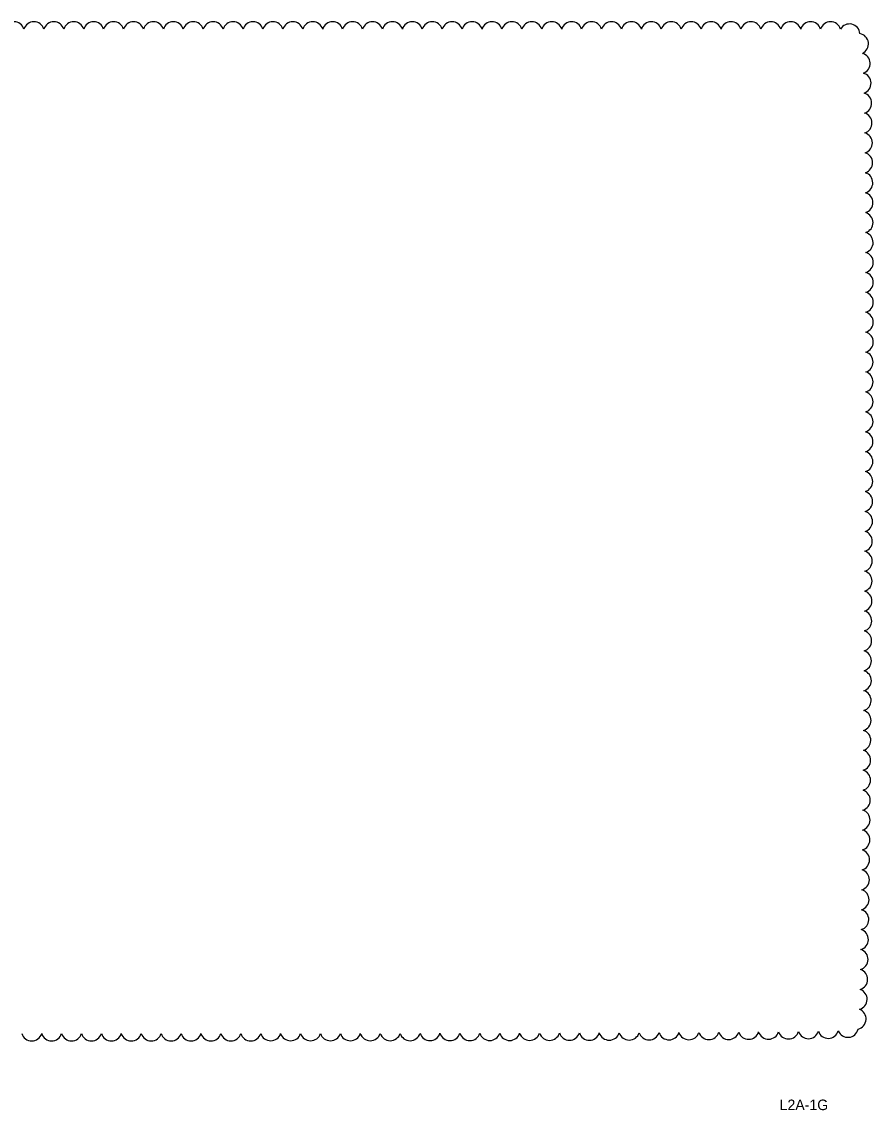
# Model space of a CAD drawing. Extents: x -811 to 10319, y -2309 to 9962.
# Drawn here: x -803.18 to -795.1, y -2284.04 to -2273.71 of the extents above; entities that cross this region are included whole.
import ezdxf

# ---------------------------------------------------------------- set-up
doc = ezdxf.new("R2010")
doc.units = 0
doc.layers.add('ScratchEle_dp', color=7, linetype='Continuous')
doc.layers.add('SheetLines_dp', color=7, linetype='Continuous')

msp = doc.modelspace()

# ---------------------------------------------------------------- linework, layer by layer
at = {"layer": 'ScratchEle_dp'}
for centre, radius, start, end in [((-803.255, -2273.807), 0.0991, 17.5008, 162.5008), ((-803.066, -2273.807), 0.0991, 17.5, 162.5), ((-802.877, -2273.807), 0.0991, 17.5, 162.5), ((-802.688, -2273.807), 0.0991, 17.5, 162.5), ((-802.499, -2273.807), 0.0991, 17.5, 162.5), ((-802.31, -2273.807), 0.0991, 17.5, 162.5), ((-802.121, -2273.807), 0.0991, 17.5, 162.5), ((-801.932, -2273.807), 0.0991, 17.5, 162.5), ((-801.743, -2273.807), 0.0991, 17.5, 162.5), ((-801.554, -2273.807), 0.0991, 17.5, 162.5), ((-801.365, -2273.807), 0.0991, 17.5, 162.5), ((-801.176, -2273.807), 0.0991, 17.5, 162.5), ((-800.987, -2273.807), 0.0991, 17.5, 162.5), ((-800.798, -2273.807), 0.0991, 17.5, 162.5), ((-800.609, -2273.807), 0.0991, 17.5, 162.5), ((-800.42, -2273.807), 0.0991, 17.5, 162.5), ((-800.231, -2273.807), 0.0991, 17.5, 162.5), ((-800.042, -2273.807), 0.0991, 17.5, 162.5), ((-799.853, -2273.807), 0.0991, 17.5, 162.5), ((-799.664, -2273.807), 0.0991, 17.5, 162.5), ((-799.475, -2273.807), 0.0991, 17.5, 162.5), ((-799.286, -2273.807), 0.0991, 17.5, 162.5), ((-799.097, -2273.807), 0.0991, 17.5, 162.5), ((-798.908, -2273.807), 0.0991, 17.5, 162.5), ((-798.719, -2273.807), 0.0991, 17.5, 162.5), ((-798.53, -2273.807), 0.0991, 17.5, 162.5), ((-798.341, -2273.807), 0.0991, 17.5, 162.5), ((-798.152, -2273.807), 0.0991, 17.5, 162.5), ((-797.963, -2273.807), 0.0991, 17.5, 162.5), ((-797.774, -2273.807), 0.0991, 17.5, 162.5), ((-797.585, -2273.807), 0.0991, 17.5, 162.5), ((-797.396, -2273.807), 0.0991, 17.5, 162.5), ((-797.207, -2273.807), 0.0991, 17.5, 162.5), ((-797.018, -2273.807), 0.0991, 17.5, 162.5), ((-796.829, -2273.807), 0.0991, 17.5, 162.5), ((-796.64, -2273.807), 0.0991, 17.5, 162.5), ((-796.451, -2273.807), 0.0991, 17.5, 162.5), ((-796.262, -2273.807), 0.0991, 17.5, 162.5), ((-796.073, -2273.807), 0.0991, 17.5, 162.5), ((-795.884, -2273.807), 0.0991, 17.5, 162.5), ((-795.695, -2273.807), 0.0991, 17.5, 162.5), ((-795.506, -2273.807), 0.0991, 17.5, 162.5), ((-795.326, -2273.828), 0.099, 4.4162, 149.4162), ((-795.245, -2273.918), 0.0992, 294.7802, 79.7802), ((-795.229, -2274.104), 0.0991, 290.3649, 75.3649), ((-795.221, -2274.292), 0.0991, 289.3839, 74.3839), ((-795.215, -2274.481), 0.0991, 288.8712, 73.8712), ((-795.212, -2274.669), 0.0991, 288.5423, 73.5423), ((-795.208, -2274.858), 0.0991, 288.3081, 73.3081), ((-795.206, -2275.047), 0.0991, 288.1304, 73.1304), ((-795.204, -2275.236), 0.0991, 287.9896, 72.9896), ((-795.203, -2275.425), 0.0991, 287.8744, 72.8744), ((-795.202, -2275.614), 0.0991, 287.778, 72.778), ((-795.201, -2275.803), 0.0991, 287.6956, 72.6956), ((-795.2, -2275.992), 0.0991, 287.6243, 72.6243), ((-795.2, -2276.181), 0.0991, 287.5617, 72.5617), ((-795.2, -2276.37), 0.0991, 287.5062, 72.5062), ((-795.2, -2276.559), 0.0991, 287.4565, 72.4565), ((-795.2, -2276.748), 0.0991, 287.4117, 72.4117), ((-795.201, -2276.937), 0.0991, 287.3711, 72.3711), ((-795.201, -2277.126), 0.0991, 287.3339, 72.3339), ((-795.202, -2277.315), 0.0991, 287.2999, 72.2999), ((-795.202, -2277.504), 0.0991, 287.2684, 72.2684), ((-795.203, -2277.693), 0.0991, 287.2394, 72.2394), ((-795.204, -2277.882), 0.0991, 287.2123, 72.2123), ((-795.205, -2278.071), 0.0991, 287.1871, 72.1871), ((-795.206, -2278.26), 0.0991, 287.1635, 72.1635), ((-795.207, -2278.449), 0.0991, 287.1414, 72.1414), ((-795.209, -2278.638), 0.0991, 287.126, 72.126), ((-795.21, -2278.827), 0.0991, 287.1162, 72.1162), ((-795.211, -2279.016), 0.0991, 287.1058, 72.1058), ((-795.212, -2279.205), 0.0991, 287.0946, 72.0946), ((-795.214, -2279.394), 0.0991, 287.0827, 72.0827), ((-795.215, -2279.583), 0.0991, 287.0698, 72.0698), ((-795.217, -2279.772), 0.0991, 287.0559, 72.0559), ((-795.218, -2279.961), 0.0991, 287.0408, 72.0408), ((-795.22, -2280.15), 0.0991, 287.0244, 72.0244), ((-795.221, -2280.338), 0.0991, 287.0064, 72.0064), ((-795.223, -2280.527), 0.0991, 286.9865, 71.9865), ((-795.225, -2280.716), 0.0991, 286.9645, 71.9645), ((-795.226, -2280.905), 0.0991, 286.94, 71.94), ((-795.228, -2281.094), 0.0991, 286.9123, 71.9123), ((-795.23, -2281.283), 0.0991, 286.8807, 71.8807), ((-795.232, -2281.472), 0.0991, 286.8443, 71.8443), ((-795.235, -2281.661), 0.0991, 286.8016, 71.8016), ((-795.237, -2281.85), 0.0991, 286.7507, 71.7507), ((-795.24, -2282.039), 0.0991, 286.6884, 71.6884), ((-795.242, -2282.228), 0.0991, 286.6098, 71.6098), ((-795.246, -2282.417), 0.0991, 286.5063, 71.5063), ((-795.249, -2282.606), 0.0991, 286.3609, 71.3609), ((-795.253, -2282.795), 0.0991, 286.1344, 71.1344), ((-795.258, -2282.984), 0.0991, 285.7012, 70.7012), ((-795.268, -2283.171), 0.099, 283.7418, 68.7418), ((-803.087, -2283.28), 0.0991, 197.4952, 342.4952), ((-802.898, -2283.28), 0.0991, 197.5007, 342.5007), ((-802.709, -2283.28), 0.0991, 197.5043, 342.5043), ((-802.52, -2283.28), 0.0991, 197.5079, 342.5079), ((-802.331, -2283.28), 0.0991, 197.5117, 342.5117), ((-802.142, -2283.28), 0.0991, 197.5156, 342.5156), ((-801.953, -2283.28), 0.0991, 197.5197, 342.5197), ((-801.764, -2283.28), 0.0991, 197.5239, 342.5239), ((-801.575, -2283.28), 0.0991, 197.5284, 342.5284), ((-801.386, -2283.28), 0.0991, 197.533, 342.533), ((-801.197, -2283.28), 0.0991, 197.5379, 342.5379), ((-801.008, -2283.28), 0.0991, 197.543, 342.543), ((-800.819, -2283.279), 0.0991, 197.5483, 342.5483), ((-800.63, -2283.279), 0.0991, 197.554, 342.554), ((-800.441, -2283.279), 0.0991, 197.5599, 342.5599), ((-800.252, -2283.279), 0.0991, 197.5662, 342.5662), ((-800.063, -2283.279), 0.0991, 197.5729, 342.5729), ((-799.874, -2283.278), 0.0991, 197.5799, 342.5799), ((-799.685, -2283.278), 0.0991, 197.5874, 342.5874), ((-799.496, -2283.278), 0.0991, 197.5954, 342.5954), ((-799.307, -2283.277), 0.0991, 197.604, 342.604), ((-799.118, -2283.277), 0.0991, 197.6131, 342.6131), ((-798.929, -2283.277), 0.0991, 197.623, 342.623), ((-798.74, -2283.276), 0.0991, 197.6337, 342.6337), ((-798.551, -2283.276), 0.0991, 197.6452, 342.6452), ((-798.362, -2283.275), 0.0991, 197.6578, 342.6578), ((-798.173, -2283.275), 0.0991, 197.6716, 342.6716), ((-797.984, -2283.274), 0.0991, 197.6868, 342.6868), ((-797.795, -2283.274), 0.0991, 197.7037, 342.7037), ((-797.606, -2283.273), 0.0991, 197.7225, 342.7225), ((-797.417, -2283.272), 0.0991, 197.7438, 342.7438), ((-797.228, -2283.271), 0.0991, 197.768, 342.768), ((-797.039, -2283.27), 0.0991, 197.796, 342.796), ((-796.85, -2283.269), 0.0991, 197.8288, 342.8288), ((-796.661, -2283.268), 0.0991, 197.8681, 342.8681), ((-796.472, -2283.267), 0.0991, 197.9161, 342.9161), ((-796.283, -2283.265), 0.0991, 197.9767, 342.9767), ((-796.094, -2283.264), 0.0991, 198.0568, 343.0568), ((-795.905, -2283.262), 0.0991, 198.1697, 343.1697), ((-795.716, -2283.259), 0.0991, 198.3466, 343.3466), ((-795.528, -2283.256), 0.0991, 198.6898, 343.6898), ((-795.341, -2283.246), 0.0992, 202.4244, 347.4244)]:
    msp.add_arc(centre, radius, start, end, dxfattribs=at)

# ---------------------------------------------------------------- texts
at = {"layer": 'SheetLines_dp'}
msp.add_text('L2A-1G', height=0.1, dxfattribs=at).set_placement((-795.989, -2284.036))

doc.saveas('drawing.dxf')
